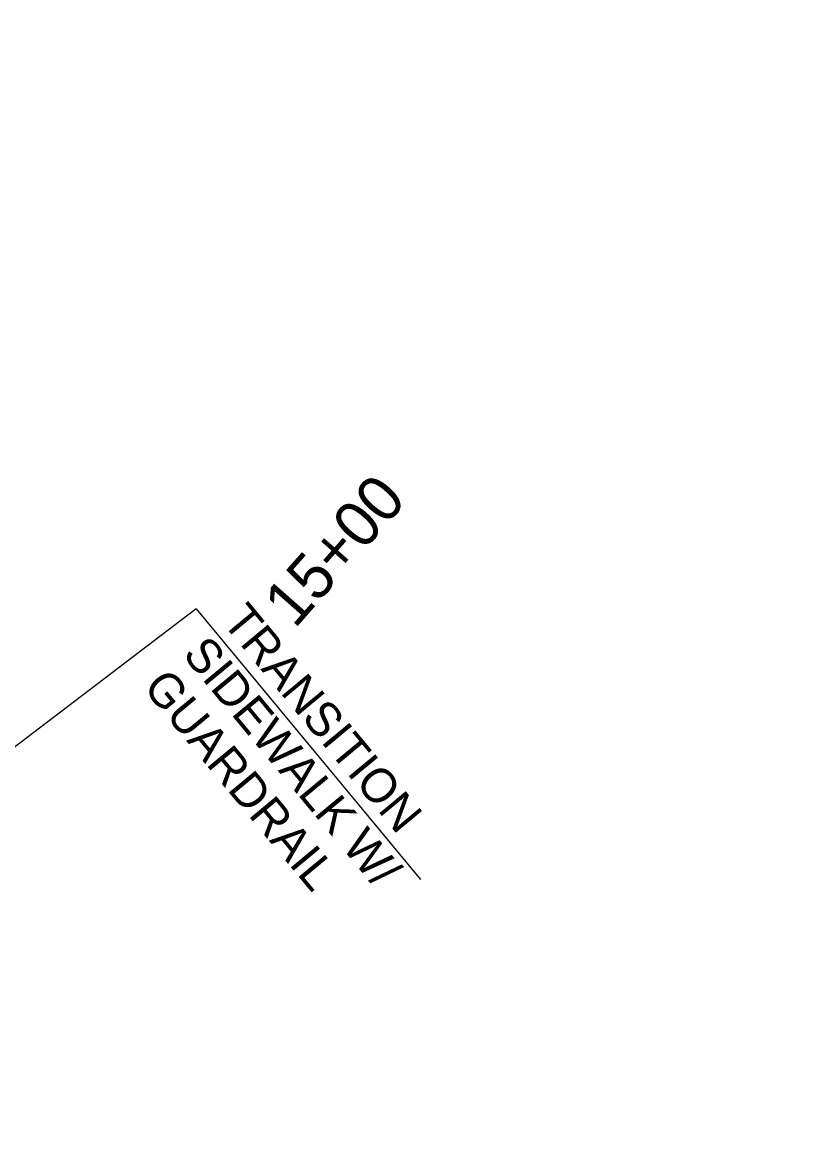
# Model space of a CAD drawing. Extents: x 2057680 to 2059216, y 687940 to 689338.
# Drawn here: x 2058782.6 to 2058902, y 688836.8 to 689006.6 of the extents above; entities that cross this region are included whole.
import ezdxf

# ---------------------------------------------------------------- set-up
doc = ezdxf.new("R2010")
doc.units = 0
for name, color, linetype in [('Cogo Default Point CELL', 7, 'Continuous'), ('Exist DTM Breakline Cogo Elevation', 7, 'Continuous'), ('Exist Other Culture Located Object CELL', 7, 'Continuous'), ('Exist Roads Soil', 7, 'Continuous'), ('Exist Structure Major Deck Tunnel Box Culvert Cogo Elevation', 7, 'Continuous'), ('Exist Structure Major Deck Tunnel Box Culvert Cogo Number', 7, 'Continuous')]:
    doc.layers.add(name, color=color, linetype=linetype)

msp = doc.modelspace()

# ---------------------------------------------------------------- linework, layer by layer
at = {"layer": 'Cogo Default Point CELL'}
msp.add_arc((2058091.57, 688086.7), 1000, 13.85856, 62.50587, dxfattribs=at)
at = {"layer": 'Exist Other Culture Located Object CELL'}
for q in [(2058709.93, 688841.13), (2058843.66, 688875.16)]:
    msp.add_line((2058809.26, 688916.65), q, dxfattribs=at)
at = {"layer": 'Exist Structure Major Deck Tunnel Box Culvert Cogo Elevation'}
msp.add_arc((2058091.57, 688086.7), 1012, 46.48931, 62.50587, dxfattribs=at)
at = {"layer": 'Exist Structure Major Deck Tunnel Box Culvert Cogo Number'}
for radius in [1012, 986]:
    msp.add_arc((2058091.57, 688086.7), radius, 13.85856, 62.50587, dxfattribs=at)

# ---------------------------------------------------------------- texts
at = {"layer": 'Exist DTM Breakline Cogo Elevation'}
for s, height, p in [(' BEGIN TIP PROJECT B-4659 ', 15, (2058782.78, 689194.27)), ('TRANSITION', 5.25, (2058813.11, 688914.63)), ('SIDEWALK W/', 5.25, (2058807.05, 688909.6)), ('GUARDRAIL', 5.25, (2058800.98, 688904.57))]:
    msp.add_text(s, height=height, rotation=309.6672, dxfattribs=at).set_placement(p)
at = {"layer": 'Exist Roads Soil'}
msp.add_text('15+00', height=7, rotation=48.6056, dxfattribs=at).set_placement((2058824.38, 688913.49))

doc.saveas('drawing.dxf')
